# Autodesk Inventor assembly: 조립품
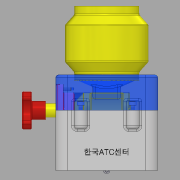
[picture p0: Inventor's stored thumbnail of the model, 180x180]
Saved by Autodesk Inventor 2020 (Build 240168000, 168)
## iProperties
Created: 2022-03
Part Number: 조립품
Document SubType Name: Assembly
Designer: Administrator
Author: Administrator
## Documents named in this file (10)
- C:\Users\Administrator\Desktop\720306V1013\조립품.iam
- C:\Users\Administrator\Desktop\720306V1013\본체.ipt
- C:\Users\Administrator\Desktop\720306V1013\핸들축.ipt
- C:\Users\Administrator\Desktop\720306V1013\앞커버.ipt
- C:\Users\Administrator\Desktop\720306V1013\베어링 부시.ipt
- C:\Users\Administrator\Desktop\720306V1013\본체커버.ipt
- C:\Users\Administrator\Desktop\720306V1013\용기.ipt
- C:\Users\Administrator\Desktop\720306V1013\핸들.ipt
- C:\Users\Administrator\Desktop\720306V1013\볼트 M3x12.ipt
- C:\Users\Administrator\Desktop\720306V1013\볼트 M4x12.ipt
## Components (2 placed, 2 different names)
1. 핸들축:1
2. 핸들:1
